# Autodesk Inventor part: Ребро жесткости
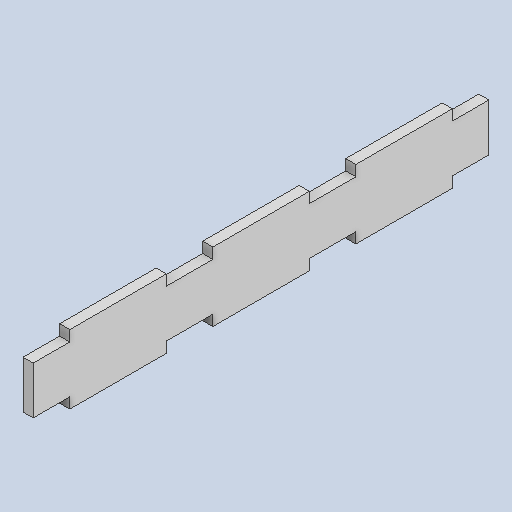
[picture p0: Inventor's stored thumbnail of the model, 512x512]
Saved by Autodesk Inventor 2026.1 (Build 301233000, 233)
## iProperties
Created: 2025-12
Part Number: Ребро жесткости
Material: Типовые
Document SubType Name: Modeling
Designer: Yury Melnikov
Density: 1 g/cm^3
Appearance: Фанера — с эффектом атмосферных воздействий
Author: Yury Melnikov
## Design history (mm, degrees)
derived "Направляющие.ipt"
feature "Ребро жесткости::Направляющие.ipt" dims "d0" = 10
tag "Элемент создания тегов1"
node "Ребро жесткости"
